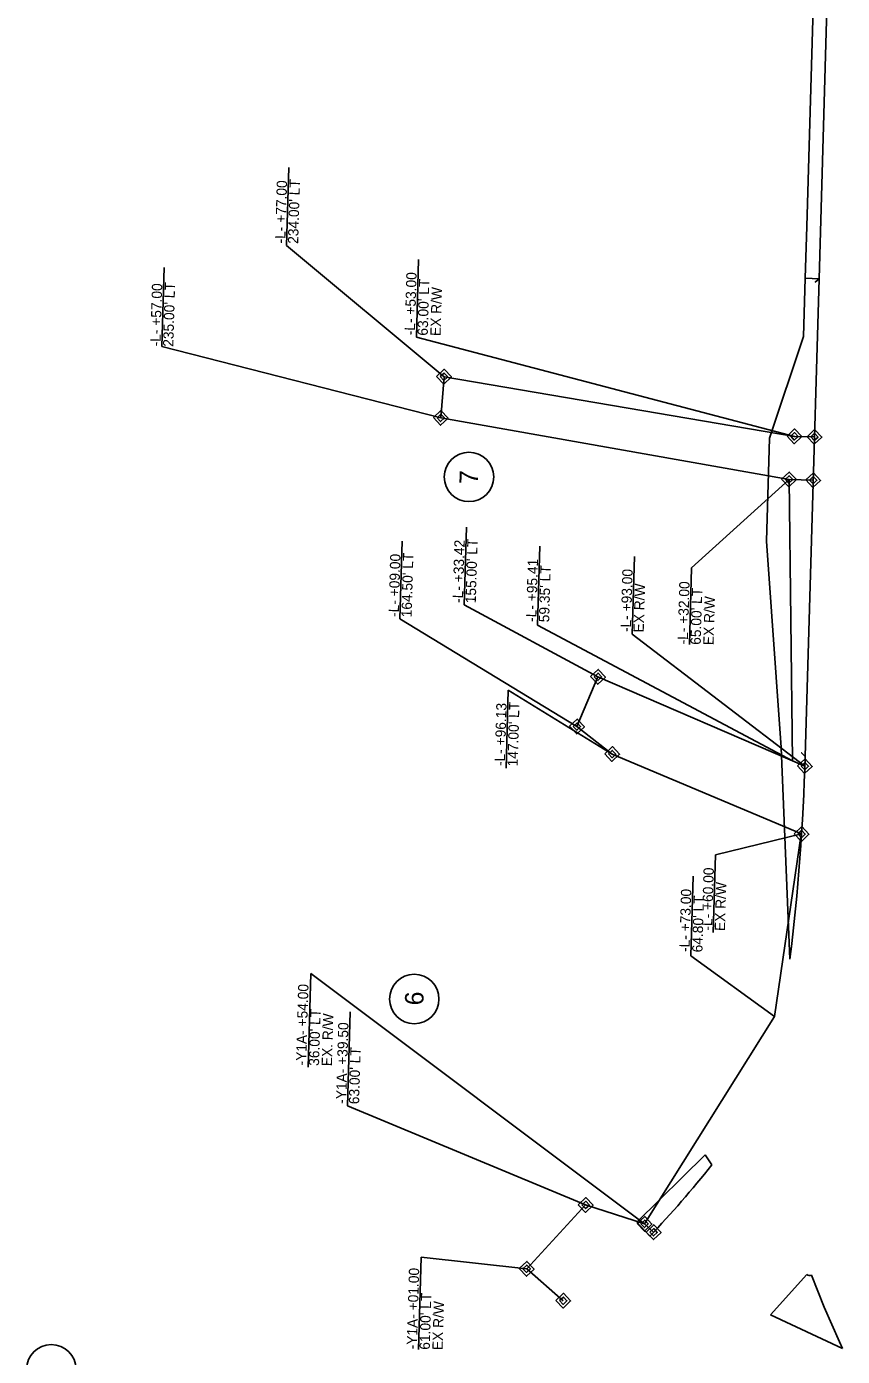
# Model space of a CAD drawing. Extents: x 2097272 to 2098144, y 685104 to 689282.
# Drawn here: x 2097272 to 2097668, y 685927 to 686573 of the extents above; entities that cross this region are included whole.
import ezdxf

# ---------------------------------------------------------------- set-up
doc = ezdxf.new("R2010")
doc.units = 0
for name, color, linetype in [('Prop Easement Construction', 7, 'Continuous'), ('Prop Easement Construction Station Offsets', 7, 'Continuous'), ('Prop Easement Permanent Drainage', 7, 'Continuous'), ('Prop Easement Permanent Drainage Station Offsets', 7, 'Continuous'), ('Prop Easement Permanent Utility', 7, 'Continuous'), ('Prop Easement Permanent Utility Station Offsets', 7, 'Continuous'), ('Prop Parcel Number CELL', 7, 'Continuous'), ('Prop ROW Marker CELL', 7, 'Continuous'), ('Prop ROW Permanent Easement CELL', 7, 'Continuous'), ('Scratch_Level_6', 7, 'Continuous')]:
    doc.layers.add(name, color=color, linetype=linetype)

msp = doc.modelspace()

# ---------------------------------------------------------------- linework, layer by layer
at = {"layer": 'Prop Easement Construction'}
for p, q in [((2097644, 686216.2), (2097642.32, 686352.89)), ((2097635.3, 686091.98), (2097648.23, 686180.6)), ((2097572.14, 685991.26), (2097635.3, 686091.98))]:
    msp.add_line(p, q, dxfattribs=at)
at = {"layer": 'Prop Easement Construction Station Offsets'}
for p, q in [((2097521.21, 686320.52), (2097520.1, 686282.1)), ((2097520.1, 686282.1), (2097644, 686216.2)), ((2097595.67, 686160.15), (2097594.54, 686121.42)), ((2097594.54, 686121.42), (2097635.3, 686091.98))]:
    msp.add_line(p, q, dxfattribs=at)
at = {"layer": 'Prop Easement Permanent Drainage'}
for p, q in [((2097473.12, 686382.82), (2097474.7, 686402.78)), ((2097644.93, 686373.82), (2097474.7, 686402.78)), ((2097642.32, 686352.89), (2097473.12, 686382.82)), ((2097654.65, 686373.54), (2097644.93, 686373.82)), ((2097654.04, 686352.55), (2097642.32, 686352.89))]:
    msp.add_line(p, q, dxfattribs=at)
at = {"layer": 'Prop Easement Permanent Drainage Station Offsets'}
for p, q in [((2097399.29, 686504.37), (2097398.19, 686466.58)), ((2097398.19, 686466.58), (2097474.7, 686402.78)), ((2097462.36, 686459.75), (2097461.26, 686421.92)), ((2097337.58, 686417.42), (2097338.7, 686455.77)), ((2097461.26, 686421.92), (2097644.93, 686373.82)), ((2097337.58, 686417.42), (2097473.12, 686382.82)), ((2097594.97, 686309.96), (2097642.32, 686352.89)), ((2097593.88, 686272.64), (2097594.97, 686309.96))]:
    msp.add_line(p, q, dxfattribs=at)
at = {"layer": 'Prop Easement Permanent Utility'}
for p, q in [((2097539.29, 686232.83), (2097549.49, 686256.97)), ((2097650, 686213.61), (2097549.49, 686256.97)), ((2097539.29, 686232.83), (2097556.4, 686219.46)), ((2097648.39, 686180.64), (2097556.4, 686219.46)), ((2097514.86, 685969.41), (2097543.5, 686000.43)), ((2097572.14, 685991.26), (2097543.5, 686000.43)), ((2097576.52, 685987.16), (2097572.14, 685991.26)), ((2097532.64, 685953.89), (2097514.86, 685969.41))]:
    msp.add_line(p, q, dxfattribs=at)
at = {"layer": 'Prop Easement Permanent Utility Station Offsets'}
for p, q in [((2097485.57, 686329.69), (2097484.48, 686291.92)), ((2097454.4, 686322.87), (2097453.3, 686285.1)), ((2097567.17, 686315.51), (2097566.07, 686277.75)), ((2097484.48, 686291.92), (2097549.49, 686256.97)), ((2097453.3, 686285.1), (2097539.29, 686232.83)), ((2097566.07, 686277.75), (2097650, 686213.61)), ((2097505.93, 686250.43), (2097504.83, 686212.66)), ((2097505.93, 686250.43), (2097556.4, 686219.46)), ((2097606.62, 686170.47), (2097648.39, 686180.64)), ((2097606.62, 686170.47), (2097605.52, 686132.7)), ((2097410.08, 686112.91), (2097408.75, 686067.34)), ((2097410.08, 686112.91), (2097572.14, 685991.26)), ((2097429.11, 686094.29), (2097427.78, 686048.58)), ((2097427.78, 686048.58), (2097543.5, 686000.43)), ((2097462.34, 685930.18), (2097463.64, 685975.11)), ((2097463.64, 685975.11), (2097514.86, 685969.41))]:
    msp.add_line(p, q, dxfattribs=at)
at = {"layer": 'Prop Parcel Number CELL'}
for centre in [(2097486.84, 686354.09), (2097460.25, 686100.47), (2097283.93, 685920.62)]:
    msp.add_circle(centre, 12, dxfattribs=at)
at = {"layer": 'Prop ROW Marker CELL'}
for p, q in [((2097474.7, 686402.78), (2097474.7, 686402.78)), ((2097473.12, 686382.82), (2097473.12, 686382.82)), ((2097644.93, 686373.82), (2097644.93, 686373.82)), ((2097654.65, 686373.54), (2097654.65, 686373.54)), ((2097642.32, 686352.89), (2097642.32, 686352.89)), ((2097654.04, 686352.55), (2097654.04, 686352.55)), ((2097549.49, 686256.97), (2097549.49, 686256.97)), ((2097539.29, 686232.83), (2097539.29, 686232.83)), ((2097556.4, 686219.46), (2097556.4, 686219.46)), ((2097650, 686213.61), (2097650, 686213.61)), ((2097648.39, 686180.64), (2097648.39, 686180.64)), ((2097543.5, 686000.43), (2097543.5, 686000.43)), ((2097572.14, 685991.26), (2097572.14, 685991.26)), ((2097576.52, 685987.16), (2097576.52, 685987.16)), ((2097514.86, 685969.41), (2097514.86, 685969.41)), ((2097532.64, 685953.89), (2097532.64, 685953.89))]:
    msp.add_line(p, q, dxfattribs=at)
at = {"layer": 'Prop ROW Permanent Easement CELL'}
for points in [[(2097471.1, 686402.88), (2097474.8, 686406.38), (2097478.29, 686402.68), (2097474.59, 686399.18)], [(2097472.9, 686402.83), (2097474.75, 686404.58), (2097476.5, 686402.73), (2097474.64, 686400.98)], [(2097469.52, 686382.92), (2097473.22, 686386.42), (2097476.71, 686382.71), (2097473.01, 686379.22)], [(2097471.32, 686382.87), (2097473.17, 686384.62), (2097474.91, 686382.77), (2097473.06, 686381.02)], [(2097641.33, 686373.92), (2097645.03, 686377.42), (2097648.52, 686373.72), (2097644.82, 686370.22)], [(2097643.13, 686373.87), (2097644.98, 686375.62), (2097646.73, 686373.77), (2097644.88, 686372.02)], [(2097651.05, 686373.64), (2097654.75, 686377.14), (2097658.25, 686373.43), (2097654.54, 686369.94)], [(2097652.85, 686373.59), (2097654.7, 686375.34), (2097656.45, 686373.49), (2097654.6, 686371.74)], [(2097638.72, 686352.99), (2097642.42, 686356.49), (2097645.92, 686352.78), (2097642.21, 686349.29)], [(2097640.52, 686352.94), (2097642.37, 686354.69), (2097644.12, 686352.84), (2097642.27, 686351.09)], [(2097650.44, 686352.65), (2097654.14, 686356.15), (2097657.64, 686352.44), (2097653.94, 686348.95)], [(2097652.24, 686352.6), (2097654.09, 686354.35), (2097655.84, 686352.49), (2097653.99, 686350.75)], [(2097545.89, 686257.07), (2097549.6, 686260.57), (2097553.09, 686256.86), (2097549.39, 686253.37)], [(2097547.69, 686257.02), (2097549.54, 686258.77), (2097551.29, 686256.92), (2097549.44, 686255.17)], [(2097535.69, 686232.94), (2097539.39, 686236.43), (2097542.88, 686232.73), (2097539.18, 686229.23)], [(2097537.49, 686232.88), (2097539.34, 686234.63), (2097541.08, 686232.78), (2097539.23, 686231.03)], [(2097552.81, 686219.56), (2097556.51, 686223.06), (2097560, 686219.35), (2097556.3, 686215.86)], [(2097554.6, 686219.51), (2097556.46, 686221.26), (2097558.2, 686219.41), (2097556.35, 686217.66)], [(2097646.4, 686213.71), (2097650.11, 686217.2), (2097653.6, 686213.5), (2097649.9, 686210.01)], [(2097648.2, 686213.66), (2097650.05, 686215.4), (2097651.8, 686213.55), (2097649.95, 686211.81)], [(2097644.79, 686180.74), (2097648.5, 686184.24), (2097651.99, 686180.53), (2097648.29, 686177.04)], [(2097646.59, 686180.69), (2097648.44, 686182.44), (2097650.19, 686180.59), (2097648.34, 686178.84)], [(2097539.91, 686000.54), (2097543.61, 686004.03), (2097547.1, 686000.33), (2097543.4, 685996.83)], [(2097541.7, 686000.48), (2097543.56, 686002.23), (2097545.3, 686000.38), (2097543.45, 685998.63)], [(2097568.55, 685991.37), (2097572.25, 685994.86), (2097575.74, 685991.16), (2097572.04, 685987.66)], [(2097570.34, 685991.31), (2097572.2, 685993.06), (2097573.94, 685991.21), (2097572.09, 685989.46)], [(2097572.92, 685987.26), (2097576.63, 685990.76), (2097580.12, 685987.05), (2097576.42, 685983.56)], [(2097574.72, 685987.21), (2097576.57, 685988.96), (2097578.32, 685987.11), (2097576.47, 685985.36)], [(2097511.26, 685969.51), (2097514.96, 685973.01), (2097518.45, 685969.3), (2097514.75, 685965.81)], [(2097513.06, 685969.46), (2097514.91, 685971.21), (2097516.66, 685969.36), (2097514.8, 685967.61)], [(2097529.04, 685953.99), (2097532.74, 685957.49), (2097536.23, 685953.78), (2097532.53, 685950.29)], [(2097530.84, 685953.94), (2097532.69, 685955.69), (2097534.43, 685953.84), (2097532.58, 685952.09)]]:
    msp.add_lwpolyline(points, close=True, dxfattribs=at)
at = {"layer": 'Scratch_Level_6'}
for p, q in [((2097656.88, 686450.41), (2097665.57, 686750.2)), ((2097650.16, 686450.73), (2097649.34, 686422.4)), ((2097656.88, 686450.41), (2097650.16, 686450.73)), ((2097650.16, 686450.73), (2097656.88, 686450.41)), ((2097649.34, 686422.4), (2097632.89, 686372.86)), ((2097632.89, 686372.86), (2097631.44, 686322.88)), ((2097631.44, 686322.88), (2097638.53, 686222.63)), ((2097638.53, 686222.63), (2097642.73, 686119.77)), ((2097601.61, 686024.77), (2097568.45, 685992.01)), ((2097604.86, 686019.9), (2097601.61, 686024.77)), ((2097568.45, 685992.01), (2097574.66, 685985.18)), ((2097650.94, 685966.66), (2097633.3, 685947)), ((2097659.33, 685950.76), (2097653.21, 685966.25)), ((2097633.3, 685947), (2097668.24, 685930.72))]:
    msp.add_line(p, q, dxfattribs=at)
for points in [[(2097660.96, 686822.23), (2097650.89, 686475.77), (2097650.16, 686450.73)], [(2097650.15, 686218.31), (2097653.19, 686323.37), (2097656.88, 686450.41)], [(2097656.88, 686450.41), (2097655.03, 686448.73), (2097656.88, 686450.41)], [(2097650.15, 686218.31), (2097648.43, 686220.13), (2097650.15, 686218.31)], [(2097668.24, 685930.72), (2097666.81, 685933.94), (2097659.33, 685950.76)]]:
    msp.add_lwpolyline(points, dxfattribs=at)
for centre, radius, start, end in [((2096580.6, 686249.32), 1070, 353.0457, 358.33912), ((2097180.74, 686358.34), 542.6, 316.54951, 321.40998), ((2097652.41, 685968.3), 2.2, 228.11169, 291.54861)]:
    msp.add_arc(centre, radius, start, end, dxfattribs=at)

# ---------------------------------------------------------------- texts
at = {"layer": 'Prop Easement Construction Station Offsets'}
for s, p in [('-L- +95.41', (2097519.52, 686283.62)), ("59.35' LT", (2097525.76, 686283.43)), ('-L- +73.00', (2097593.97, 686123.24)), ("64.80' LT", (2097600.22, 686123.06))]:
    msp.add_text(s, height=5, rotation=88.33483, dxfattribs=at).set_placement(p)
at = {"layer": 'Prop Easement Permanent Drainage Station Offsets'}
for s, p in [('-L- +77.00', (2097397.59, 686467.47)), ("234.00' LT", (2097403.84, 686467.28)), ('-L- +53.00', (2097460.54, 686422.85)), ("63.00' LT", (2097466.79, 686422.67)), ('-L- +57.00', (2097336.96, 686417.44)), ("235.00' LT", (2097343.2, 686417.26)), ('EX R/W', (2097473.03, 686422.49)), ('-L- +32.00', (2097593.13, 686272.66)), ("65.00' LT", (2097599.38, 686272.48)), ('EX R/W', (2097605.63, 686272.3))]:
    msp.add_text(s, height=5, rotation=88.33483, dxfattribs=at).set_placement(p)
at = {"layer": 'Prop Easement Permanent Utility Station Offsets'}
for s, p in [('-L- +33.42', (2097483.88, 686292.84)), ("155.00' LT", (2097490.13, 686292.66)), ('-L- +09.00', (2097452.7, 686286.02)), ("164.50' LT", (2097458.95, 686285.84)), ('-L- +93.00', (2097565.47, 686278.66)), ('EX R/W', (2097571.72, 686278.48)), ('-L- +96.13', (2097504.23, 686213.58)), ("147.00' LT", (2097510.48, 686213.4)), ('-L- +60.00', (2097604.92, 686133.62)), ('EX R/W', (2097611.17, 686133.44)), ('-Y1A- +54.00', (2097407.73, 686068.12)), ("36.00' LT", (2097413.98, 686067.94)), ('EX. R/W', (2097420.23, 686067.76)), ('-Y1A- +39.50', (2097427.18, 686049.49)), ("63.00' LT", (2097433.43, 686049.31)), ('-Y1A- +01.00', (2097461.53, 685930.2)), ("61.00' LT", (2097467.77, 685930.02)), ('EX R/W', (2097474.02, 685929.84))]:
    msp.add_text(s, height=5, rotation=88.33483, dxfattribs=at).set_placement(p)
at = {"layer": 'Prop Parcel Number CELL'}
for s, p in [('7', (2097491.16, 686350.46)), ('6', (2097464.66, 686097.29))]:
    msp.add_text(s, height=9, rotation=88.33483, dxfattribs=at).set_placement(p)

doc.saveas('drawing.dxf')
